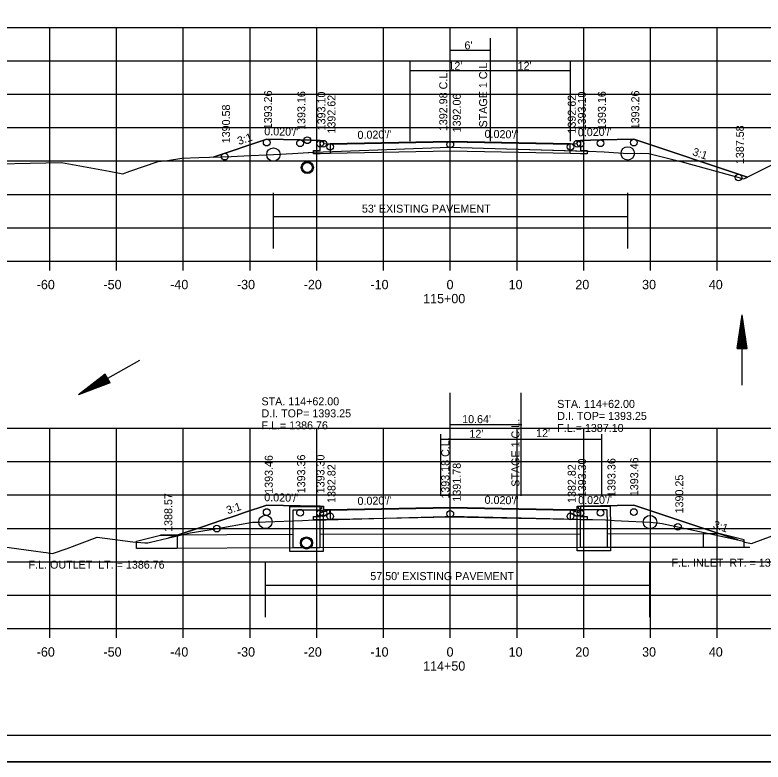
# Model space of a CAD drawing. Extents: x 1374311 to 1383814, y 384102 to 406278.
# Drawn here: x 1382655.6 to 1382767.7, y 387679.3 to 387791.1 of the extents above; entities that cross this region are included whole.
import ezdxf

# ---------------------------------------------------------------- set-up
doc = ezdxf.new("R2010")
doc.units = 0
for name, color, linetype in [('R_Axis', 7, 'Continuous'), ('R_Axis Annot', 7, 'Continuous'), ('R_Border', 7, 'Continuous'), ('R_Draft', 7, 'Continuous'), ('R_Exist Surface', 7, 'Continuous'), ('R_Fin Surface', 7, 'Continuous'), ('R_Grid', 7, 'Continuous'), ('R_No Plot', 7, 'Continuous'), ('R_Water', 7, 'Continuous'), ('R_Water Annot', 7, 'Continuous'), ('R_Xsect Elev', 7, 'Continuous'), ('R_Xsect Slope', 7, 'Continuous')]:
    doc.layers.add(name, color=color, linetype=linetype)

msp = doc.modelspace()

# ---------------------------------------------------------------- linework, layer by layer
at = {"layer": 'R_Axis'}
for p, q in [((1382580.86, 387754.27), (1382860.86, 387754.27)), ((1382660.86, 387752.87), (1382660.86, 387754.27)), ((1382670.86, 387752.87), (1382670.86, 387754.27)), ((1382680.86, 387752.87), (1382680.86, 387754.27)), ((1382690.86, 387752.87), (1382690.86, 387754.27)), ((1382700.86, 387752.87), (1382700.86, 387754.27)), ((1382710.86, 387752.87), (1382710.86, 387754.27)), ((1382720.86, 387752.87), (1382720.86, 387754.27)), ((1382730.86, 387752.87), (1382730.86, 387754.27)), ((1382740.86, 387752.87), (1382740.86, 387754.27)), ((1382750.86, 387752.87), (1382750.86, 387754.27)), ((1382760.86, 387752.87), (1382760.86, 387754.27)), ((1382580.86, 387699.27), (1382860.86, 387699.27)), ((1382660.86, 387697.87), (1382660.86, 387699.27)), ((1382670.86, 387697.87), (1382670.86, 387699.27)), ((1382680.86, 387697.87), (1382680.86, 387699.27)), ((1382690.86, 387697.87), (1382690.86, 387699.27)), ((1382700.86, 387697.87), (1382700.86, 387699.27)), ((1382710.86, 387697.87), (1382710.86, 387699.27)), ((1382720.86, 387697.87), (1382720.86, 387699.27)), ((1382730.86, 387697.87), (1382730.86, 387699.27)), ((1382740.86, 387697.87), (1382740.86, 387699.27)), ((1382750.86, 387697.87), (1382750.86, 387699.27)), ((1382760.86, 387697.87), (1382760.86, 387699.27))]:
    msp.add_line(p, q, dxfattribs=at)
at = {"layer": 'R_Border'}
msp.add_line((1382879.04, 387683.27), (1382562.86, 387683.27), dxfattribs=at)
at = {"layer": 'R_Draft'}
for p, q in [((1382763.83, 387741.22), (1382764.58, 387746.22)), ((1382765.33, 387741.22), (1382764.58, 387746.22)), ((1382763.96, 387741.22), (1382764.58, 387745.38)), ((1382764.09, 387741.22), (1382764.58, 387744.52)), ((1382765.21, 387741.22), (1382764.58, 387745.38)), ((1382765.08, 387741.22), (1382764.58, 387744.52)), ((1382764.21, 387741.22), (1382764.58, 387743.69)), ((1382764.96, 387741.22), (1382764.58, 387743.69)), ((1382764.34, 387741.22), (1382764.58, 387742.84)), ((1382764.83, 387741.22), (1382764.58, 387742.84)), ((1382763.83, 387741.22), (1382765.33, 387741.22)), ((1382764.47, 387741.22), (1382764.58, 387742.01)), ((1382764.7, 387741.22), (1382764.58, 387742.01)), ((1382669.14, 387737.36), (1382665.15, 387734.26)), ((1382669.2, 387737.25), (1382665.88, 387734.67)), ((1382669.27, 387737.14), (1382666.63, 387735.09)), ((1382669.33, 387737.03), (1382667.35, 387735.5)), ((1382669.39, 387736.92), (1382668.09, 387735.91)), ((1382669.63, 387736.5), (1382668.09, 387735.91)), ((1382669.45, 387736.81), (1382668.82, 387736.32)), ((1382669.57, 387736.61), (1382668.82, 387736.32)), ((1382669.88, 387736.05), (1382669.14, 387737.36)), ((1382669.88, 387736.05), (1382665.15, 387734.26)), ((1382669.82, 387736.16), (1382665.88, 387734.67)), ((1382669.75, 387736.27), (1382666.63, 387735.09)), ((1382669.69, 387736.38), (1382667.35, 387735.5))]:
    msp.add_line(p, q, dxfattribs=at)
at = {"layer": 'R_Exist Surface'}
for points in [[(1382648.54, 387768.74), (1382662.59, 387769.05), (1382669.77, 387767.77), (1382671.81, 387767.34), (1382672.85, 387767.74), (1382677.07, 387769.18), (1382678.5, 387769.33), (1382680.62, 387769.68), (1382683.16, 387769.77), (1382688.04, 387769.96), (1382689.92, 387770.05), (1382694.35, 387770.23), (1382697.23, 387770.4), (1382700.44, 387770.6), (1382711.33, 387771), (1382720.69, 387771.33), (1382729.29, 387771.1), (1382741.57, 387770.75), (1382743.89, 387770.62), (1382747.44, 387770.41), (1382749.52, 387770.44), (1382750.63, 387770.4), (1382755.38, 387769.17), (1382764.84, 387766.58), (1382769.52, 387768.93)], [(1382647.75, 387712.33), (1382658.41, 387710.9), (1382659.84, 387710.71), (1382660.29, 387710.68), (1382661.27, 387710.52), (1382663.48, 387711.27), (1382667.95, 387712.93), (1382673.3, 387712.27), (1382675.09, 387712.09), (1382675.55, 387712.09), (1382675.94, 387712.18), (1382681.89, 387713.6), (1382685.66, 387714.18), (1382691.21, 387715.21), (1382692.27, 387715.22), (1382693.16, 387715.24), (1382698.72, 387715.47), (1382700.45, 387715.53), (1382702.24, 387715.57), (1382720.07, 387716.03), (1382721.49, 387716.06), (1382722.95, 387716.04), (1382742.18, 387715.61), (1382744.1, 387715.54), (1382745.47, 387715.47), (1382750.78, 387715.2), (1382752.24, 387715.04), (1382752.61, 387715.02), (1382759.59, 387713.52), (1382764.57, 387712.4), (1382764.99, 387712.2), (1382766.01, 387711.98), (1382771.77, 387714.13)]]:
    msp.add_lwpolyline(points, dxfattribs=at)
for centre in [(1382699.44, 387768.3), (1382699.32, 387712.08), (1382699.32, 387712.08)]:
    msp.add_circle(centre, 0.917, dxfattribs=at)
at = {"layer": 'R_Fin Surface'}
for points in [[(1382685.34, 387769.85), (1382693.35, 387772.52), (1382698.35, 387772.42), (1382701.35, 387772.36), (1382701.85, 387772.36), (1382701.86, 387771.86), (1382702.86, 387771.88), (1382720.86, 387772.24), (1382738.86, 387771.88), (1382739.86, 387771.86), (1382739.87, 387772.36), (1382740.37, 387772.36), (1382743.37, 387772.42), (1382748.37, 387772.52), (1382765.39, 387766.85)], [(1382740.37, 387772.36), (1382740.38, 387770.83), (1382741.38, 387770.83), (1382741.37, 387770.33), (1382740.37, 387770.35), (1382738.83, 387770.38), (1382738.82, 387771.72), (1382720.86, 387772.07), (1382702.85, 387771.72), (1382702.85, 387770.38), (1382701.35, 387770.35), (1382700.35, 387770.33), (1382700.36, 387770.83), (1382701.36, 387770.83), (1382701.35, 387772.36)], [(1382678.67, 387712.84), (1382682.68, 387714.17), (1382683.86, 387714.57), (1382686.47, 387715.43), (1382688.76, 387716.2), (1382690.02, 387716.62), (1382693.35, 387717.73), (1382698.35, 387717.63), (1382701.35, 387717.57), (1382701.85, 387717.57), (1382701.86, 387717.07), (1382702.86, 387717.09), (1382720.86, 387717.45), (1382738.86, 387717.09), (1382739.86, 387717.07), (1382739.87, 387717.57), (1382740.37, 387717.57), (1382743.37, 387717.63), (1382748.37, 387717.73), (1382755.99, 387715.19), (1382758.54, 387714.34), (1382763.95, 387712.54)], [(1382740.37, 387717.57), (1382740.38, 387716.03), (1382741.38, 387716.04), (1382741.37, 387715.54), (1382740.37, 387715.56), (1382738.87, 387715.59), (1382738.87, 387716.92), (1382720.86, 387717.28), (1382702.87, 387716.92), (1382702.87, 387715.59), (1382701.35, 387715.56), (1382700.35, 387715.54), (1382700.36, 387716.04), (1382701.36, 387716.03), (1382701.35, 387717.57)]]:
    msp.add_lwpolyline(points, dxfattribs=at)
at = {"layer": 'R_Grid'}
for p, q in [((1382580.86, 387789.27), (1382860.86, 387789.27)), ((1382660.86, 387754.27), (1382660.86, 387789.27)), ((1382670.86, 387754.27), (1382670.86, 387789.27)), ((1382680.86, 387754.27), (1382680.86, 387789.27)), ((1382690.86, 387754.27), (1382690.86, 387789.27)), ((1382700.86, 387754.27), (1382700.86, 387789.27)), ((1382710.86, 387754.27), (1382710.86, 387789.27)), ((1382720.86, 387754.27), (1382720.86, 387789.27)), ((1382730.86, 387754.27), (1382730.86, 387789.27)), ((1382740.86, 387754.27), (1382740.86, 387789.27)), ((1382750.86, 387754.27), (1382750.86, 387789.27)), ((1382760.86, 387754.27), (1382760.86, 387789.27)), ((1382580.86, 387784.27), (1382860.86, 387784.27)), ((1382580.86, 387779.27), (1382860.86, 387779.27)), ((1382580.86, 387774.27), (1382860.86, 387774.27)), ((1382580.86, 387769.27), (1382860.86, 387769.27)), ((1382580.86, 387764.27), (1382860.86, 387764.27)), ((1382580.86, 387759.27), (1382860.86, 387759.27)), ((1382580.86, 387754.27), (1382860.86, 387754.27)), ((1382580.86, 387729.27), (1382860.86, 387729.27)), ((1382660.86, 387699.27), (1382660.86, 387729.27)), ((1382670.86, 387699.27), (1382670.86, 387729.27)), ((1382680.86, 387699.27), (1382680.86, 387729.27)), ((1382690.86, 387699.27), (1382690.86, 387729.27)), ((1382700.86, 387699.27), (1382700.86, 387729.27)), ((1382710.86, 387699.27), (1382710.86, 387729.27)), ((1382720.86, 387699.27), (1382720.86, 387729.27)), ((1382730.86, 387699.27), (1382730.86, 387729.27)), ((1382740.86, 387699.27), (1382740.86, 387729.27)), ((1382750.86, 387699.27), (1382750.86, 387729.27)), ((1382760.86, 387699.27), (1382760.86, 387729.27)), ((1382580.86, 387724.27), (1382860.86, 387724.27)), ((1382580.86, 387719.27), (1382860.86, 387719.27)), ((1382580.86, 387714.27), (1382860.86, 387714.27)), ((1382580.86, 387709.27), (1382860.86, 387709.27)), ((1382580.86, 387704.27), (1382860.86, 387704.27)), ((1382580.86, 387699.27), (1382860.86, 387699.27))]:
    msp.add_line(p, q, dxfattribs=at)
at = {"layer": 'R_No Plot'}
msp.add_line((1382550.46, 387679.29), (1382883.79, 387679.29), dxfattribs=at)
for points in [[(1382550.45, 387892.62), (1382883.79, 387892.62), (1382883.79, 387679.29), (1382550.45, 387679.29)], [(1382796.78, 387888.73), (1382796.78, 387878.85), (1382832.51, 387878.85), (1382832.51, 387875.93), (1382855.71, 387875.93), (1382855.71, 387852.71), (1382879.04, 387852.71), (1382879.04, 387683.27), (1382562.86, 387683.27), (1382562.86, 387888.73)], [(1382685.34, 387769.85), (1382688.04, 387769.96), (1382689.92, 387770.05), (1382694.35, 387770.23), (1382697.23, 387770.4), (1382700.36, 387770.59), (1382700.36, 387770.83), (1382701.36, 387770.83), (1382701.35, 387772.36), (1382698.35, 387772.42), (1382693.35, 387772.52)], [(1382741.38, 387770.75), (1382741.57, 387770.75), (1382743.89, 387770.62), (1382747.44, 387770.41), (1382749.52, 387770.44), (1382750.63, 387770.4), (1382755.38, 387769.17), (1382764.84, 387766.58), (1382765.39, 387766.85), (1382748.37, 387772.52), (1382743.37, 387772.42), (1382740.37, 387772.36), (1382740.38, 387770.83), (1382741.38, 387770.83)], [(1382700.36, 387770.59), (1382700.44, 387770.6), (1382711.33, 387771), (1382720.69, 387771.33), (1382729.29, 387771.1), (1382741.38, 387770.75), (1382741.37, 387770.33), (1382740.37, 387770.35), (1382738.83, 387770.38), (1382720.86, 387770.74), (1382702.85, 387770.38), (1382702.85, 387770.38), (1382701.35, 387770.35), (1382700.35, 387770.33)], [(1382678.67, 387712.84), (1382681.89, 387713.6), (1382685.66, 387714.18), (1382691.21, 387715.21), (1382692.27, 387715.22), (1382693.16, 387715.24), (1382698.72, 387715.47), (1382700.45, 387715.53), (1382702.24, 387715.57), (1382703.81, 387715.61), (1382702.87, 387715.59), (1382701.35, 387715.56), (1382700.35, 387715.54), (1382700.36, 387716.04), (1382701.36, 387716.03), (1382701.35, 387717.57), (1382698.35, 387717.63), (1382693.35, 387717.73), (1382690.02, 387716.62), (1382688.76, 387716.2), (1382686.47, 387715.43), (1382683.86, 387714.57), (1382682.68, 387714.17)], [(1382741.37, 387715.62), (1382742.18, 387715.61), (1382744.1, 387715.54), (1382745.47, 387715.47), (1382750.78, 387715.2), (1382752.24, 387715.04), (1382752.61, 387715.02), (1382759.59, 387713.52), (1382763.95, 387712.54), (1382758.54, 387714.34), (1382755.99, 387715.19), (1382748.37, 387717.73), (1382743.37, 387717.63), (1382740.37, 387717.57), (1382740.38, 387716.03), (1382741.38, 387716.04)], [(1382703.81, 387715.61), (1382720.07, 387716.03), (1382721.49, 387716.06), (1382722.95, 387716.04), (1382741.37, 387715.62), (1382741.37, 387715.54), (1382740.37, 387715.56), (1382738.87, 387715.59), (1382720.86, 387715.95)]]:
    msp.add_lwpolyline(points, close=True, dxfattribs=at)
for centre, radius in [((1382693.35, 387772.02), 0.5), ((1382698.35, 387771.92), 0.5), ((1382699.44, 387772.37), 0.5), ((1382701.35, 387771.86), 0.5), ((1382701.85, 387771.86), 0.5), ((1382739.87, 387771.86), 0.5), ((1382740.37, 387771.86), 0.5), ((1382743.37, 387771.92), 0.5), ((1382748.37, 387772.02), 0.5), ((1382694.35, 387770.23), 1), ((1382702.86, 387771.38), 0.5), ((1382720.86, 387771.74), 0.5), ((1382738.86, 387771.38), 0.5), ((1382747.44, 387770.41), 1), ((1382687.06, 387769.92), 0.5), ((1382687.06, 387769.92), 0.5), ((1382764.05, 387766.8), 0.5), ((1382693.35, 387716.71), 0.5), ((1382698.35, 387716.61), 0.5), ((1382701.35, 387716.55), 0.5), ((1382701.85, 387716.55), 0.5), ((1382702.86, 387716.07), 0.5), ((1382720.86, 387716.43), 0.5), ((1382738.86, 387716.07), 0.5), ((1382739.87, 387716.55), 0.5), ((1382740.37, 387716.55), 0.5), ((1382743.37, 387716.61), 0.5), ((1382748.37, 387716.71), 0.5), ((1382693.16, 387715.24), 1), ((1382750.78, 387715.2), 1), ((1382685.89, 387714.23), 0.5), ((1382685.89, 387714.23), 0.5), ((1382754.97, 387714.51), 0.5)]:
    msp.add_circle(centre, radius, dxfattribs=at)
at = {"layer": 'R_Water'}
for p, q in [((1382720.86, 387784.28), (1382720.86, 387787.66)), ((1382726.86, 387772.24), (1382726.86, 387787.66)), ((1382720.86, 387785.85), (1382726.86, 387785.85)), ((1382714.86, 387772.24), (1382714.86, 387784.33)), ((1382738.86, 387772.24), (1382738.86, 387784.33)), ((1382714.86, 387782.81), (1382738.86, 387782.81)), ((1382720.86, 387772.24), (1382720.86, 387782.2)), ((1382694.35, 387756.16), (1382694.35, 387764.48)), ((1382747.44, 387756.16), (1382747.44, 387764.48)), ((1382694.35, 387760.95), (1382747.44, 387760.95)), ((1382764.58, 387735.71), (1382764.58, 387746.22)), ((1382674.31, 387739.41), (1382665.15, 387734.26)), ((1382720.86, 387719.12), (1382720.86, 387734.54)), ((1382731.5, 387719.12), (1382731.5, 387734.54)), ((1382720.86, 387729.83), (1382731.56, 387729.83)), ((1382719.42, 387719.12), (1382719.42, 387728.36)), ((1382719.43, 387727.64), (1382743.55, 387727.64)), ((1382743.55, 387719.12), (1382743.55, 387728.36)), ((1382696.82, 387717.52), (1382701.58, 387717.52)), ((1382696.82, 387716.02), (1382696.82, 387717.52)), ((1382701.66, 387717.35), (1382701.58, 387717.52)), ((1382740.04, 387717.35), (1382740.12, 387717.52)), ((1382744.87, 387717.52), (1382740.12, 387717.52)), ((1382744.87, 387716.02), (1382744.87, 387717.52)), ((1382697.32, 387716.02), (1382697.32, 387717.02)), ((1382697.32, 387717.02), (1382701.32, 387717.02)), ((1382701.66, 387717.35), (1382701.32, 387717.02)), ((1382702.83, 387717.04), (1382701.32, 387716.52)), ((1382701.32, 387716.02), (1382701.32, 387716.52)), ((1382702.83, 387716.51), (1382701.82, 387716.16)), ((1382738.87, 387717.04), (1382740.37, 387716.52)), ((1382738.87, 387716.51), (1382739.87, 387716.16)), ((1382740.04, 387717.35), (1382740.37, 387717.02)), ((1382744.37, 387717.02), (1382740.37, 387717.02)), ((1382740.37, 387716.02), (1382740.37, 387716.52)), ((1382744.37, 387716.02), (1382744.37, 387717.02)), ((1382701.82, 387716.02), (1382701.82, 387716.16)), ((1382739.87, 387716.02), (1382739.87, 387716.16)), ((1382697.32, 387713.34), (1382677.46, 387713.25)), ((1382740.37, 387713.42), (1382701.32, 387713.34)), ((1382761.27, 387713.43), (1382744.37, 387713.42)), ((1382697.32, 387711.33), (1382677.47, 387711.24)), ((1382740.37, 387711.41), (1382701.32, 387711.33)), ((1382744.87, 387710.91), (1382739.87, 387710.91)), ((1382765.76, 387711.42), (1382744.37, 387711.41)), ((1382693.16, 387700.95), (1382693.16, 387709.27)), ((1382750.78, 387700.95), (1382750.78, 387709.27)), ((1382693.16, 387705.74), (1382750.78, 387705.74))]:
    msp.add_line(p, q, dxfattribs=at)
for points in [[(1382702.83, 387716.51), (1382702.83, 387717.04)], [(1382738.87, 387716.51), (1382738.87, 387717.04)], [(1382701.82, 387716.02), (1382701.82, 387710.83), (1382699.32, 387710.83), (1382696.82, 387710.83), (1382696.82, 387716.02)], [(1382701.32, 387716.02), (1382701.32, 387711.33), (1382699.32, 387711.33), (1382697.32, 387711.33), (1382697.32, 387716.02)], [(1382739.87, 387710.91), (1382739.87, 387716.02)], [(1382740.37, 387711.41), (1382740.37, 387716.02)], [(1382744.37, 387716.02), (1382744.37, 387711.41)], [(1382744.87, 387716.02), (1382744.87, 387710.91)], [(1382744.37, 387711.41), (1382742.37, 387711.41), (1382740.37, 387711.41)]]:
    msp.add_lwpolyline(points, dxfattribs=at)
for points in [[(1382679.96, 387713.25), (1382679.96, 387711.25), (1382673.83, 387711.25), (1382673.83, 387712.37), (1382677.46, 387713.25)], [(1382758.77, 387713.43), (1382758.77, 387711.43), (1382764.9, 387711.43), (1382764.9, 387712.55), (1382761.27, 387713.43)]]:
    msp.add_lwpolyline(points, close=True, dxfattribs=at)
for centre in [(1382699.44, 387768.3), (1382699.32, 387712.08), (1382699.32, 387712.08)]:
    msp.add_circle(centre, 0.75, dxfattribs=at)

# ---------------------------------------------------------------- texts
at = {"layer": 'R_Axis Annot'}
for s, p in [('-60', (1382658.9, 387750.07)), ('-50', (1382668.9, 387750.07)), ('-40', (1382678.9, 387750.07)), ('-30', (1382688.9, 387750.07)), ('-20', (1382698.9, 387750.07)), ('-10', (1382708.9, 387750.07)), ('0', (1382720.3, 387750.07)), ('10', (1382729.6, 387750.07)), ('20', (1382739.6, 387750.07)), ('30', (1382749.6, 387750.07)), ('40', (1382759.6, 387750.07)), ('115+00', (1382716.8, 387747.97)), ('-60', (1382658.9, 387695.07)), ('-50', (1382668.9, 387695.07)), ('-40', (1382678.9, 387695.07)), ('-30', (1382688.9, 387695.07)), ('-20', (1382698.9, 387695.07)), ('-10', (1382708.9, 387695.07)), ('0', (1382720.3, 387695.07)), ('10', (1382729.6, 387695.07)), ('20', (1382739.6, 387695.07)), ('30', (1382749.6, 387695.07)), ('40', (1382759.6, 387695.07)), ('114+50', (1382716.8, 387692.97))]:
    msp.add_text(s, height=1.4, dxfattribs=at).set_placement(p)
at = {"layer": 'R_Water'}
for s, p in [("6'", (1382722.98, 387785.98)), ("12'", (1382720.58, 387782.92)), ("12'", (1382730.95, 387782.92)), ("53' EXISTING PAVEMENT", (1382707.62, 387761.54)), ("10.64'", (1382722.64, 387730.02)), ("12'", (1382723.73, 387727.83)), ("12'", (1382733.72, 387727.93)), ('F.L. INLET  RT. = 1387.10', (1382754.02, 387708.53)), ('F.L. OUTLET  LT. = 1386.76', (1382657.68, 387708.24)), ("57.50' EXISTING PAVEMENT", (1382708.88, 387706.52))]:
    msp.add_text(s, height=1.2, dxfattribs=at).set_placement(p)
for p in [(1382726.38, 387774.29), (1382731.22, 387720.5)]:
    msp.add_text('STAGE 1 C.L.', height=1.2, rotation=90, dxfattribs=at).set_placement(p)
at = {"layer": 'R_Water Annot'}
for s, p in [('STA. 114+62.00', (1382692.57, 387732.69)), ('STA. 114+62.00', (1382736.88, 387732.3)), ('D.I. TOP= 1393.25', (1382692.57, 387730.89)), ('D.I. TOP= 1393.25', (1382736.88, 387730.5)), ('F.L.= 1386.76', (1382692.57, 387729.09)), ('F.L.= 1387.10', (1382736.88, 387728.7))]:
    msp.add_text(s, height=1.2, dxfattribs=at).set_placement(p)
at = {"layer": 'R_Xsect Elev'}
for s, p in [('1392.98 C.L.', (1382720.41, 387773.74)), ('1393.26', (1382694.15, 387774.02)), ('1393.16', (1382699.15, 387773.92)), ('1393.10', (1382702.15, 387773.86)), ('1392.62', (1382703.66, 387773.38)), ('1392.06', (1382722.43, 387773.56)), ('1392.62', (1382739.66, 387773.38)), ('1393.10', (1382741.17, 387773.86)), ('1393.16', (1382744.17, 387773.92)), ('1393.26', (1382749.17, 387774.02)), ('1390.58', (1382687.86, 387771.92)), ('1387.58', (1382764.85, 387768.8)), ('1393.18 C.L.', (1382720.71, 387718.72)), ('1393.46', (1382694.26, 387719.44)), ('1393.36', (1382699.12, 387719.52)), ('1393.30', (1382702.01, 387719.52)), ('1393.30', (1382741.2, 387718.93)), ('1393.36', (1382745.61, 387718.98)), ('1393.46', (1382749.02, 387719.09)), ('1382.82', (1382703.66, 387718.07)), ('1391.78', (1382722.43, 387718.28)), ('1382.82', (1382739.66, 387718.07)), ('1390.25', (1382755.77, 387716.51)), ('1388.57', (1382679.21, 387713.74))]:
    msp.add_text(s, height=1.2, rotation=90, dxfattribs=at).set_placement(p)
at = {"layer": 'R_Xsect Slope'}
for s, rotation, p in [("0.020'/'", 358.8542, (1382692.98, 387773.13)), ("0.020'/'", 1.1458, (1382706.97, 387772.57)), ("0.020'/'", 358.8542, (1382725.99, 387772.74)), ("0.020'/'", 1.1458, (1382739.98, 387772.96)), ('3:1', 18.4349, (1382689.19, 387771.66)), ('3:1', 341.5651, (1382757.04, 387770.16)), ("0.020'/'", 358.8542, (1382692.98, 387718.34)), ("0.020'/'", 1.1458, (1382706.97, 387717.77)), ("0.020'/'", 358.8542, (1382725.99, 387717.95)), ("0.020'/'", 1.1458, (1382740.03, 387717.88)), ('3:1', 18.4338, (1382687.53, 387716.36)), ('3:1', 341.5655, (1382760.13, 387714.34))]:
    msp.add_text(s, height=1.2, rotation=rotation, dxfattribs=at).set_placement(p)

doc.saveas('drawing.dxf')
